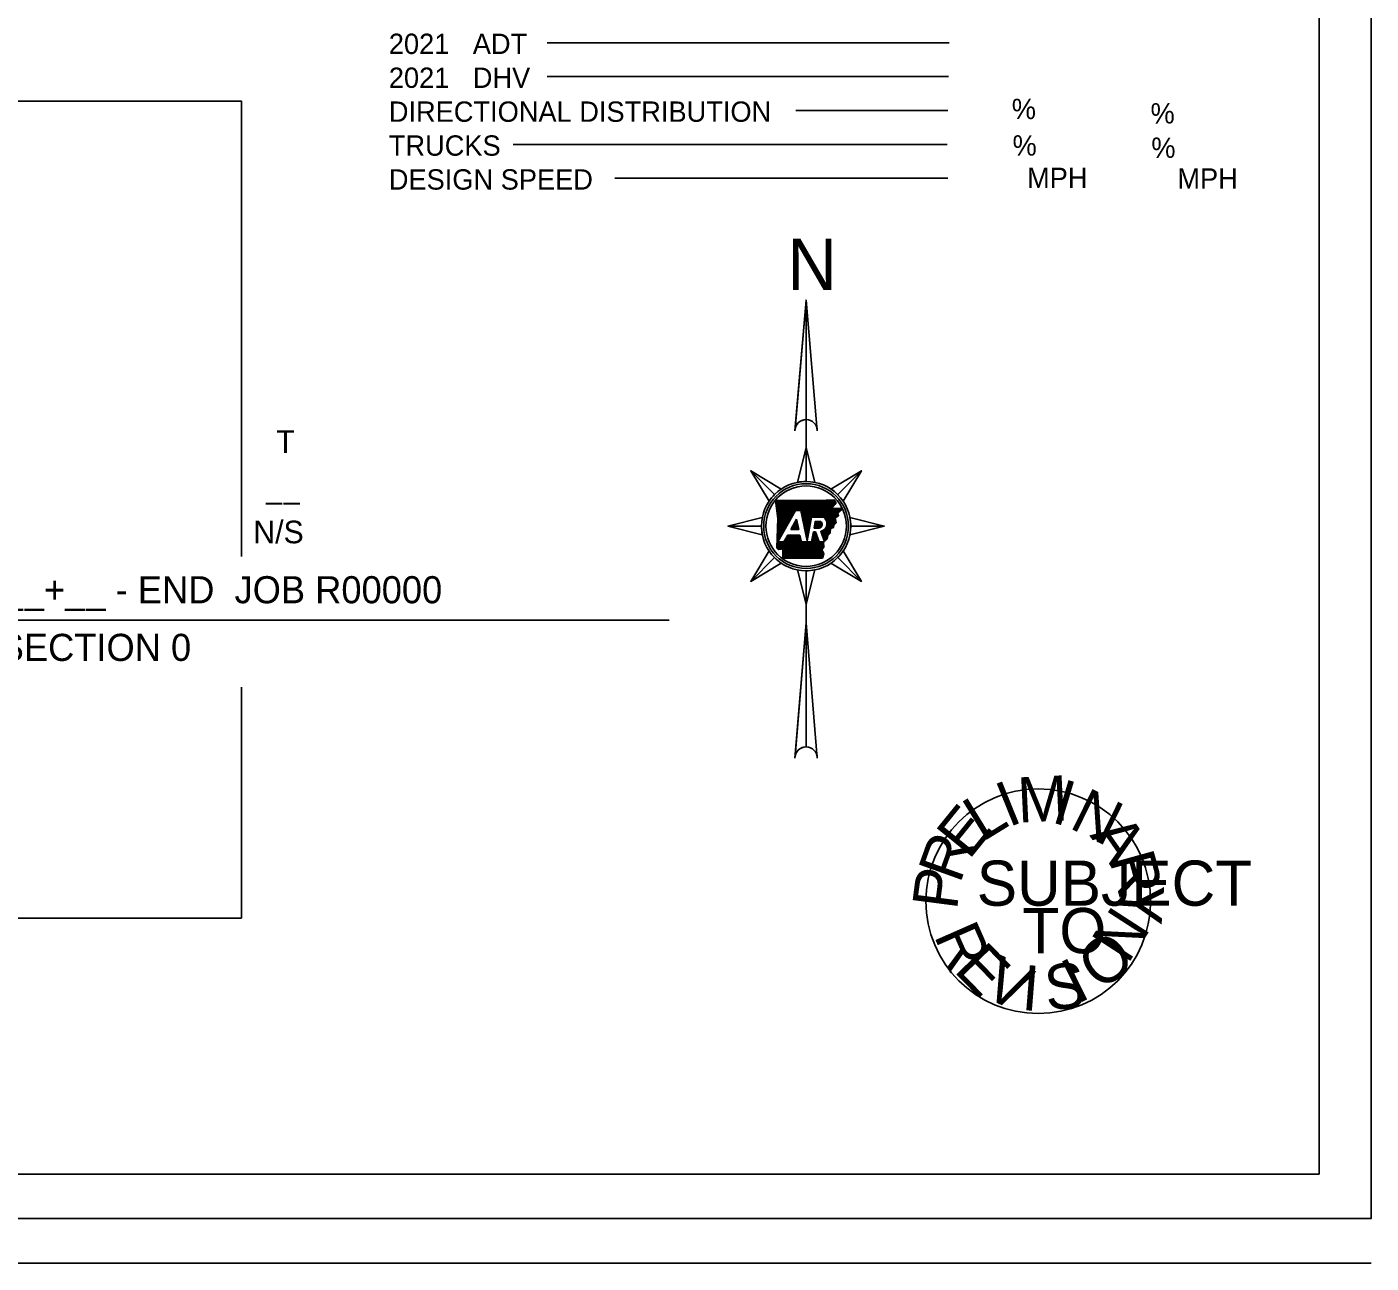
# Model space of a CAD drawing. Extents: x 76 to 6945, y -3933 to 2152.
# Drawn here: x 4651 to 5840, y -3583 to -2489 of the extents above; entities that cross this region are included whole.
import ezdxf

# ---------------------------------------------------------------- set-up
doc = ezdxf.new("R2010")
doc.units = 0
doc.layers.add('R_Draft', color=7, linetype='Continuous')
doc.layers.add('R_No Plot', color=7, linetype='Continuous')

msp = doc.modelspace()

# ---------------------------------------------------------------- linework, layer by layer
at = {"layer": 'R_Draft'}
for p, q in [((5794.4, -3504), (5794.4, -1449.6)), ((5111.3, -2503), (5467.2, -2503)), ((5111.3, -2533), (5466.6, -2533)), ((5331.3, -2563), (5465.9, -2563)), ((5081.3, -2593), (5465.3, -2593)), ((5171.3, -2623), (5465.9, -2623)), ((5340.5, -2730.8), (5330.8, -2844.8)), ((5340.5, -2730.8), (5340.5, -2886.9)), ((5340.5, -2836.6), (5340.5, -2730.8)), ((5331, -2842.6), (5331.9, -2841.7)), ((5330.9, -2843.2), (5331.3, -2842.7)), ((5340.5, -2861.5), (5332.8, -2891.9)), ((5340.5, -2891.2), (5340.5, -2861.5)), ((5291.6, -2881.8), (5312.6, -2902.8)), ((5312.6, -2902.8), (5291.6, -2881.8)), ((5291.6, -2881.8), (5307.7, -2908.7)), ((5389.4, -2881.8), (5362.5, -2897.9)), ((5368.5, -2902.8), (5389.4, -2881.8)), ((5368.5, -2902.8), (5389.4, -2881.8)), ((5313.6, -2908.4), (5313.9, -2908.1)), ((5313.7, -2909.4), (5315, -2908.1)), ((5313.8, -2910.4), (5316.2, -2908.1)), ((5313.9, -2911.4), (5317.3, -2908.1)), ((5314.1, -2912.4), (5318.4, -2908.1)), ((5314.2, -2913.4), (5319.5, -2908.1)), ((5314.3, -2914.4), (5320.6, -2908.1)), ((5314.4, -2915.4), (5321.7, -2908.1)), ((5314.6, -2916.4), (5322.9, -2908.1)), ((5314.7, -2917.4), (5324, -2908.1)), ((5314.8, -2918.4), (5325.1, -2908.1)), ((5314.9, -2919.4), (5326.2, -2908.1)), ((5315.1, -2920.4), (5327.3, -2908.1)), ((5315.2, -2932.5), (5339.6, -2908.1)), ((5315.2, -2921.4), (5328.4, -2908.1)), ((5315.3, -2931.3), (5338.5, -2908.1)), ((5315.3, -2930.2), (5337.4, -2908.1)), ((5315.3, -2929), (5336.3, -2908.1)), ((5315.3, -2922.3), (5329.6, -2908.1)), ((5315.4, -2927.9), (5335.2, -2908.1)), ((5315.4, -2926.7), (5334, -2908.1)), ((5315.4, -2925.6), (5332.9, -2908.1)), ((5315.4, -2923.3), (5330.7, -2908.1)), ((5315.5, -2924.4), (5331.8, -2908.1)), ((5331.8, -2917), (5340.8, -2908.1)), ((5332.9, -2917), (5341.9, -2908.1)), ((5334, -2917), (5343, -2908.1)), ((5335.2, -2917), (5344.1, -2908)), ((5335.9, -2917.4), (5345.3, -2908)), ((5336.1, -2918.4), (5346.4, -2908)), ((5336.3, -2919.3), (5347.5, -2908)), ((5336.5, -2920.2), (5348.7, -2908)), ((5336.7, -2921.1), (5349.8, -2907.9)), ((5336.8, -2922), (5351, -2907.9)), ((5337, -2923), (5352.1, -2907.9)), ((5337.2, -2923.9), (5353.2, -2907.9)), ((5337.4, -2924.8), (5354.4, -2907.9)), ((5337.6, -2925.7), (5355.5, -2907.9)), ((5337.8, -2926.6), (5356.6, -2907.8)), ((5338, -2927.6), (5357.8, -2907.8)), ((5338.2, -2928.5), (5358.9, -2907.8)), ((5338.4, -2929.4), (5360.1, -2907.8)), ((5346.2, -2922.8), (5361.2, -2907.7)), ((5347.3, -2922.8), (5362.3, -2907.7)), ((5348.4, -2922.8), (5363.5, -2907.7)), ((5349.5, -2922.8), (5364.6, -2907.7)), ((5350.7, -2922.8), (5365.8, -2907.6)), ((5351.8, -2922.8), (5366, -2908.5)), ((5352.9, -2922.8), (5366.6, -2909.1)), ((5354, -2922.8), (5366.7, -2910.1)), ((5355.1, -2922.8), (5364.2, -2913.7)), ((5315.1, -2934.8), (5328.8, -2921.1)), ((5315.1, -2936), (5327.3, -2923.7)), ((5315.2, -2933.6), (5330.3, -2918.6)), ((5315.5, -2944.5), (5331.1, -2917)), ((5327, -2933.7), (5332.1, -2924.7)), ((5331.1, -2917), (5335.8, -2917)), ((5331.3, -2926.1), (5332.2, -2925.2)), ((5338.6, -2930.3), (5345, -2924)), ((5338.8, -2931.2), (5344.7, -2925.3)), ((5345.2, -2922.8), (5356, -2922.8)), ((5354.1, -2937.2), (5366.5, -2924.8)), ((5354.4, -2938), (5366.7, -2925.7)), ((5356.1, -2922.9), (5363.9, -2915.1)), ((5356.8, -2923.4), (5365.1, -2915)), ((5357.3, -2923.9), (5366.3, -2914.9)), ((5357.8, -2924.6), (5367.5, -2914.9)), ((5357.8, -2932.4), (5366.3, -2923.9)), ((5358.2, -2925.3), (5368.6, -2914.8)), ((5358.5, -2926.1), (5369.8, -2914.8)), ((5358.7, -2930.3), (5368.9, -2920.2)), ((5358.8, -2926.9), (5370.9, -2914.8)), ((5359, -2927.9), (5371.4, -2915.4)), ((5359, -2929), (5368.7, -2919.2)), ((5367.6, -2922.6), (5369, -2921.2)), ((5370.9, -2917), (5371.9, -2916)), ((5409.7, -2930.7), (5379.3, -2923)), ((5271.3, -2930.7), (5301, -2930.7)), ((5301, -2930.7), (5271.3, -2930.7)), ((5271.3, -2930.7), (5301.7, -2938.4)), ((5314.9, -2940.6), (5321.5, -2934)), ((5314.9, -2941.7), (5320, -2936.6)), ((5315, -2938.3), (5324.4, -2928.9)), ((5315, -2939.4), (5323, -2931.5)), ((5315.1, -2937.1), (5325.9, -2926.3)), ((5327, -2933.7), (5334, -2933.7)), ((5327.1, -2933.7), (5332.8, -2928)), ((5328.2, -2933.7), (5333, -2928.9)), ((5328.4, -2931.3), (5332.6, -2927.1)), ((5329.3, -2933.7), (5333.2, -2929.8)), ((5329.9, -2928.7), (5332.4, -2926.2)), ((5330.4, -2933.7), (5333.4, -2930.8)), ((5331.5, -2933.7), (5333.6, -2931.7)), ((5332.7, -2933.7), (5333.8, -2932.6)), ((5333.8, -2933.7), (5334, -2933.5)), ((5339, -2932.2), (5344.5, -2926.7)), ((5339.2, -2933.1), (5344.3, -2928)), ((5339.4, -2934), (5344, -2929.4)), ((5339.6, -2934.9), (5343.8, -2930.7)), ((5339.8, -2935.8), (5343.5, -2932.1)), ((5340, -2936.8), (5343.3, -2933.5)), ((5340.2, -2937.7), (5343.1, -2934.8)), ((5340.4, -2938.6), (5342.8, -2936.2)), ((5340.6, -2939.5), (5342.6, -2937.5)), ((5346.1, -2940.7), (5349.4, -2937.4)), ((5346.3, -2939.4), (5349.1, -2936.6)), ((5346.6, -2938), (5348.8, -2935.8)), ((5346.8, -2936.7), (5347.7, -2935.8)), ((5348.8, -2935.8), (5347, -2935.8)), ((5347.5, -2932.5), (5353.4, -2926.6)), ((5347.5, -2932.5), (5352.2, -2932.5)), ((5347.8, -2931.2), (5352.3, -2926.6)), ((5348, -2929.8), (5351.2, -2926.6)), ((5348.2, -2928.5), (5350.1, -2926.6)), ((5348.5, -2927.1), (5348.9, -2926.6)), ((5348.6, -2926.6), (5353.6, -2926.6)), ((5348.7, -2932.5), (5354, -2927.1)), ((5352.1, -2944.5), (5348.8, -2935.8)), ((5349.8, -2932.5), (5354.4, -2927.9)), ((5350.9, -2932.5), (5354.6, -2928.8)), ((5352, -2932.5), (5354.5, -2930)), ((5353.4, -2935.3), (5356.8, -2944.5)), ((5353.5, -2935.6), (5353.8, -2935.2)), ((5353.8, -2936.4), (5355.9, -2934.2)), ((5354.7, -2938.8), (5366.9, -2926.6)), ((5355, -2939.6), (5367.1, -2927.5)), ((5355.3, -2940.5), (5362, -2933.8)), ((5355.6, -2941.3), (5361.9, -2935)), ((5355.9, -2942.1), (5361.8, -2936.2)), ((5363.3, -2932.5), (5364.9, -2930.9)), ((5380, -2930.7), (5409.7, -2930.7)), ((5380, -2930.7), (5409.7, -2930.7)), ((5314.7, -2949.8), (5319.9, -2944.5)), ((5314.7, -2948.7), (5318.8, -2944.5)), ((5314.7, -2947.5), (5317.7, -2944.5)), ((5314.8, -2944.1), (5317.1, -2941.8)), ((5314.8, -2945.2), (5315.7, -2944.3)), ((5314.8, -2946.4), (5316.6, -2944.5)), ((5314.9, -2942.9), (5318.6, -2939.2)), ((5315.1, -2950.5), (5326.8, -2938.8)), ((5320.9, -2944.5), (5315.5, -2944.5)), ((5315.7, -2951), (5327.9, -2938.8)), ((5316.5, -2951.3), (5329.1, -2938.8)), ((5317.9, -2951.1), (5330.2, -2938.8)), ((5319, -2951.1), (5331.3, -2938.8)), ((5319.9, -2953.5), (5334.6, -2938.8)), ((5319.9, -2952.4), (5333.5, -2938.8)), ((5319.9, -2951.3), (5332.4, -2938.8)), ((5319.9, -2954.6), (5335.2, -2939.3)), ((5319.9, -2955.7), (5335.4, -2940.2)), ((5319.9, -2956.8), (5335.6, -2941.1)), ((5319.9, -2958), (5335.8, -2942.1)), ((5319.9, -2959.1), (5336, -2943)), ((5324.2, -2938.8), (5320.9, -2944.5)), ((5321.1, -2959.1), (5336.2, -2943.9)), ((5322.2, -2942.3), (5325.7, -2938.8)), ((5322.2, -2959.1), (5336.7, -2944.5)), ((5323.3, -2959.1), (5337.8, -2944.5)), ((5323.6, -2939.7), (5324.6, -2938.8)), ((5335.1, -2938.8), (5324.2, -2938.8)), ((5324.4, -2959.1), (5338.9, -2944.5)), ((5325.5, -2959.1), (5340, -2944.5)), ((5326.6, -2959.1), (5341.2, -2944.5)), ((5327.8, -2959.1), (5342.3, -2944.5)), ((5328.9, -2959.1), (5343.4, -2944.5)), ((5330, -2959.1), (5344.5, -2944.5)), ((5331.1, -2959.1), (5350.3, -2939.8)), ((5332.2, -2959.1), (5350.6, -2940.7)), ((5333.3, -2959.1), (5350.9, -2941.5)), ((5334.5, -2959.1), (5351.2, -2942.3)), ((5335.6, -2959.1), (5351.5, -2943.1)), ((5345.4, -2944.5), (5336.4, -2944.5)), ((5336.7, -2959.1), (5351.8, -2943.9)), ((5337.8, -2959.1), (5352.3, -2944.5)), ((5338.9, -2959.1), (5353.5, -2944.5)), ((5340, -2959.1), (5354.6, -2944.5)), ((5340.8, -2940.5), (5342.4, -2938.9)), ((5341, -2941.4), (5342.1, -2940.2)), ((5341.2, -2942.3), (5341.9, -2941.6)), ((5341.2, -2959.1), (5355.7, -2944.5)), ((5341.4, -2943.2), (5341.7, -2942.9)), ((5342.3, -2959.1), (5356.1, -2945.3)), ((5343.4, -2959.1), (5356.1, -2946.4)), ((5344.5, -2959.1), (5356.2, -2947.4)), ((5345.6, -2943.4), (5350, -2939)), ((5345.6, -2959.1), (5356.2, -2948.5)), ((5345.9, -2942.1), (5349.7, -2938.2)), ((5356.8, -2944.5), (5352.1, -2944.5)), ((5356.2, -2942.9), (5359.6, -2939.5)), ((5356.5, -2943.7), (5359.2, -2941.1)), ((5291.6, -2979.6), (5312.6, -2958.6)), ((5312.6, -2958.6), (5291.6, -2979.6)), ((5346.7, -2959.1), (5354.4, -2951.4)), ((5347.8, -2959.1), (5354.7, -2952.2)), ((5349, -2959.1), (5355.1, -2953)), ((5350.1, -2959.1), (5355.4, -2953.8)), ((5351.2, -2959.1), (5355.8, -2954.5)), ((5352.3, -2959.1), (5356.1, -2955.4)), ((5353.4, -2959.1), (5355.5, -2957)), ((5354.5, -2959.1), (5355, -2958.6)), ((5368.5, -2958.6), (5389.4, -2979.6)), ((5368.5, -2958.6), (5389.4, -2979.6)), ((5389.4, -2979.6), (5373.4, -2952.7)), ((5291.6, -2979.6), (5318.5, -2963.6)), ((5340.5, -2999.9), (5348.2, -2969.5)), ((5340.5, -2970.2), (5340.5, -2970.2)), ((5340.5, -2970.2), (5340.5, -3096.7)), ((5340.5, -2970.2), (5340.5, -2999.9)), ((4551.5, -3014), (5219.4, -3014)), ((5340.5, -3016.4), (5330.8, -3134.3)), ((5340.5, -3126.1), (5340.5, -3016.4)), ((5794.4, -3504), (2632.6, -3504)), ((2566.9, -3543.4), (5840.4, -3543.4)), ((2566.9, -3582.8), (5840.4, -3582.8))]:
    msp.add_line(p, q, dxfattribs=at)
for points in [[(3569.2, -2736.5), (3569.2, -2554.6), (4840.9, -2554.6), (4840.9, -2957.5)], [(5350.4, -2846.4), (5340.5, -2730.8), (5330.6, -2846.4)], [(4840.9, -3073.1), (4840.9, -3277.5), (3569.2, -3277.5), (3569.2, -2841.8)], [(5332.8, -2891.9), (5340.5, -2861.5), (5348.2, -2891.9)], [(5307.7, -2908.7), (5291.6, -2881.8), (5318.5, -2897.9)], [(5362.5, -2897.9), (5389.4, -2881.8), (5373.4, -2908.7)], [(5313.5, -2908.1), (5328.9, -2908.1), (5342.5, -2908.1), (5358.4, -2907.8), (5365.8, -2907.6)], [(5314.6, -2949.8), (5315.5, -2923.9), (5313.5, -2908.1)], [(5301.7, -2938.4), (5271.3, -2930.7), (5301.7, -2923)], [(5332.1, -2924.7), (5334, -2933.7)], [(5335.8, -2917), (5341.5, -2943.8), (5345.2, -2922.8)], [(5370.7, -2914.7), (5372, -2916.1), (5368.7, -2918.9), (5369.1, -2921.6), (5366.2, -2923.5), (5367.2, -2927.7), (5365, -2929.8), (5364.8, -2931.9), (5362.1, -2932.9), (5361.7, -2937), (5359.8, -2939.1), (5358.8, -2942.2), (5356, -2944.7), (5356.3, -2949.3), (5354.4, -2951.4), (5356.1, -2955.3), (5354.9, -2959.1)], [(5363.6, -2915.1), (5370.8, -2914.7)], [(5379.3, -2923), (5409.7, -2930.7), (5379.3, -2938.4)], [(5347, -2935.8), (5345.4, -2944.5)], [(5347.5, -2932.5), (5348.6, -2926.6)], [(5336.4, -2944.5), (5335.1, -2938.8)], [(5318.5, -2963.6), (5291.6, -2979.6), (5307.7, -2952.7)], [(5354.9, -2959.1), (5319.9, -2959.1), (5319.9, -2951.3)], [(5373.4, -2952.7), (5389.4, -2979.6), (5362.5, -2963.6)], [(5348.2, -2969.5), (5340.5, -2999.9), (5332.8, -2969.5)], [(5350.4, -3135.9), (5340.5, -3016.4), (5330.6, -3135.9)]]:
    msp.add_lwpolyline(points, dxfattribs=at)
for centre, radius in [((5340.5, -2930.7), 39.5), ((5340.5, -2930.7), 37.5), ((5340.5, -2930.7), 35.6), ((5545.9, -3262.6), 99.4)]:
    msp.add_circle(centre, radius, dxfattribs=at)
for centre, radius, start, end in [((5340.5, -2846.4), 9.88, 0, 180), ((5340.5, -2846.4), 9.88, 90, 170.2296), ((5340.5, -2930.7), 39.5, 90, 101.2291), ((5340.5, -2930.7), 39.5, 45, 56.2291), ((5340.5, -2930.7), 39.5, 135, 146.2291), ((5352, -2928.5), 7, 281.8626, 54.8705), ((5340.5, -2930.7), 39.5, 0, 11.2291), ((5340.5, -2930.7), 39.5, 180, 191.2291), ((5351.1, -2929.1), 3.58, 288.1268, 43.8902), ((5340.5, -2930.7), 39.5, 225, 236.2291), ((5340.5, -2930.7), 39.5, 315, 326.2291), ((5340.5, -2930.7), 39.5, 270, 281.2291), ((5340.5, -3135.9), 9.88, 0, 180), ((5340.5, -3135.9), 9.88, 90, 170.5511)]:
    msp.add_arc(centre, radius, start, end, dxfattribs=at)
for points in [[(5365.8, -2907.6), (5365.9, -2908.1), (5366, -2908.3), (5366, -2908.7), (5366.2, -2908.9), (5366.5, -2909), (5366.7, -2909.3), (5366.8, -2909.6), (5366.7, -2910), (5366.7, -2910.3), (5366.7, -2910.7), (5366.6, -2911), (5366.4, -2911.2), (5366.1, -2911.4), (5365.9, -2911.6), (5365.8, -2911.8), (5365.6, -2912), (5365.3, -2912.2), (5365.1, -2912.4), (5364.9, -2912.7), (5364.8, -2913), (5364.6, -2913.2), (5364.4, -2913.4), (5364.2, -2913.7), (5364.1, -2913.9), (5363.9, -2914.2), (5363.8, -2914.5), (5363.7, -2914.7), (5363.7, -2914.8)], [(5319.9, -2951.3), (5320, -2951.4), (5319.8, -2951.2), (5319.5, -2951.1), (5319.2, -2951.1), (5318.9, -2951), (5318.6, -2951), (5318.3, -2950.8), (5318, -2951), (5317.6, -2951.2), (5317.4, -2951), (5317.1, -2951.1), (5316.9, -2951.1), (5316.6, -2951.3), (5316.3, -2951.2), (5316.1, -2951.3), (5315.8, -2951.3), (5315.7, -2950.9), (5315.4, -2950.9), (5315.2, -2950.8), (5315, -2950.4), (5314.9, -2950.2), (5314.6, -2949.8)]]:
    msp.add_spline(points, degree=3, dxfattribs=at)
at = {"layer": 'R_No Plot'}
msp.add_lwpolyline([(2557, -1410.1), (5840.4, -1410.1), (5840.4, -3543.4), (2557, -3543.4)], close=True, dxfattribs=at)

# ---------------------------------------------------------------- texts
at = {"layer": 'R_Draft'}
for s, height, p in [('2021', 18, (4971.3, -2513)), (' ADT', 18, (5038.9, -2513)), ('2021', 18, (4971.3, -2543)), (' DHV', 18, (5038.9, -2543)), ('DIRECTIONAL DISTRIBUTION', 18, (4971.3, -2573)), ('  %', 18, (5509.1, -2570.6)), ('   %', 18, (5625.2, -2574.5)), ('TRUCKS', 18, (4971.3, -2603)), ('  %', 18, (5509.8, -2602.9)), ('   %', 18, (5625.9, -2604.9)), ('DESIGN SPEED', 18, (4971.3, -2633)), (' MPH', 18, (5529.3, -2631.6)), (' MPH', 18, (5662.3, -2632.2)), ('N', 45.6, (5323.8, -2721.9)), ('T', 20, (4871.7, -2865.9)), ('__', 20, (4862.7, -2905.9)), ('N/S', 20, (4851.4, -2945.9)), ('DWB 7-27-17', 0.768, (5338.1, -2966.9)), ('STA. __+__ - END  JOB R00000', 24, (4550.3, -2999)), ('END SECTION 0', 24, (4550.3, -3050)), ('SUBJECT', 40, (5491.5, -3266.6)), ('TO', 40, (5531.9, -3308.6))]:
    msp.add_text(s, height=height, dxfattribs=at).set_placement(p)
for s, rotation, p in [('M', 2.6943, (5528.3, -3193.1)), ('I', 22.0105, (5519.6, -3197.5)), ('I', 343.3781, (5556.5, -3192.4)), ('N', 333.7199, (5572.2, -3197.3)), ('L', 31.6686, (5496.4, -3210.6)), ('E', 50.9849, (5484.5, -3226.7)), ('A', 304.7456, (5591, -3204.3)), ('R', 70.3011, (5476.6, -3247.8)), ('R', 285.4294, (5608.3, -3224.6)), ('P', 82.6089, (5473.9, -3271.1)), ('Y', 266.1131, (5617.5, -3246.1)), ('N', 57.1378, (5625, -3319)), ('R', 293.7639, (5453.2, -3292.9)), ('O', 36.5754, (5600.7, -3342.8)), ('E', 314.3262, (5470.4, -3324.2)), ('V', 334.8885, (5495.2, -3346)), ('S', 5.732, (5553.5, -3359.4)), ('I', 26.2943, (5580.3, -3353.9)), ('I', 355.4508, (5530.4, -3358.7))]:
    msp.add_text(s, height=40, rotation=rotation, dxfattribs=at).set_placement(p)

doc.saveas('drawing.dxf')
